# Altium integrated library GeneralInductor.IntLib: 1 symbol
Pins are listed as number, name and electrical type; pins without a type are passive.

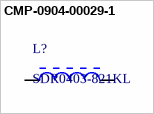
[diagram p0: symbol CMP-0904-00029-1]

## CMP-0904-00029-1
designator L?, comment SDR0403-821KL
SDR0403 Series Power Inductor, 820 uF +/- 10 %, 12 Ohm, -40 to 125 degC, 2-Pin SMD, RoHS, Tape and Reel; Manufacturer: Bourns; I sat (A): 0.15 Typ.; Q: 38; Test Frequency (MHz): 0.796; SRF (MHz): 2.5 Min.; Inductance (uH): 820; Tolerance (%): +/- 10; RDC (Ohm): 12 Max.; I rms (A): 0.1 Max.
footprint BOUR-SDR0403-2_V (SMD, 2-Leads, Dia 4.5mm, Height 3.5mm)
pins: 1, 2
